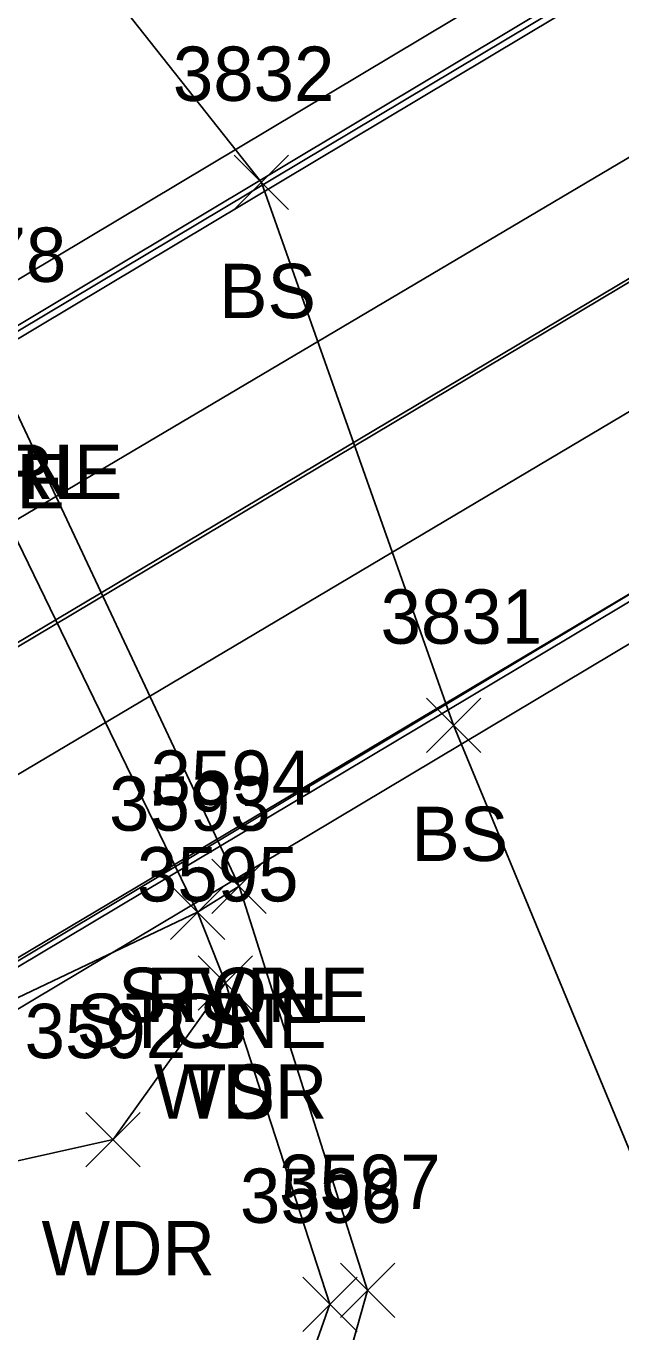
# Model space of a CAD drawing. Extents: x 1443590 to 1445966, y 578314 to 580556.
# Drawn here: x 1444226.98 to 1444248.89, y 578924.11 to 578972.2 of the extents above; entities that cross this region are included whole.
import ezdxf

# ---------------------------------------------------------------- set-up
doc = ezdxf.new("R2010")
doc.units = 0
for name, color, linetype in [('BB', 7, 'Continuous'), ('BDC', 7, 'Continuous'), ('BELB', 7, 'Continuous'), ('BF', 7, 'Continuous'), ('L_A', 7, 'Continuous'), ('L_I', 7, 'Continuous'), ('L_TIC', 7, 'Continuous'), ('LASF', 7, 'Continuous'), ('LAWA', 7, 'Continuous'), ('LAWE', 7, 'Continuous'), ('LELB', 7, 'Continuous')]:
    doc.layers.add(name, color=color, linetype=linetype)

msp = doc.modelspace()

# ---------------------------------------------------------------- linework, layer by layer
at = {"layer": 'BB'}
for points in [[(1444205.61, 578948.082), (1444265.76, 578984.059)], [(1444208.51, 578943.3), (1444268.791, 578978.975)], [(1444210.663, 578939.803), (1444271.012, 578975.796)], [(1444212.663, 578936.329), (1444272.861, 578972.041)], [(1444215.703, 578931.366), (1444275.895, 578967.159)]]:
    msp.add_lwpolyline(points, dxfattribs=at)
at = {"layer": 'BDC'}
for points in [[(1444393.513, 579062.489), (1444394.118, 579061.308), (1444330.705, 579023.404), (1444267.078, 578985.387), (1444205.127, 578948.274), (1444203.399, 578948.665), (1444203.223, 578948.843)], [(1444405.354, 579042.696), (1444404.549, 579043.555), (1444341.218, 579006.037), (1444277.67, 578968.005), (1444214.55, 578930.312), (1444214.603, 578929.77), (1444215.047, 578929.061)]]:
    msp.add_lwpolyline(points, dxfattribs=at)
at = {"layer": 'BELB'}
for points in [[(1444394.46, 579061.264), (1444330.853, 579023.124), (1444267.263, 578985.215), (1444204.094, 578947.486)], [(1444399.314, 579053.056), (1444336.08, 579014.873), (1444272.042, 578976.518), (1444209.069, 578939.026)], [(1444404.648, 579044.232), (1444341.196, 579006.183), (1444277.507, 578968.231), (1444214.381, 578930.41)]]:
    msp.add_lwpolyline(points, dxfattribs=at)
at = {"layer": 'BF'}
for points in [[(1444393.513, 579062.489), (1444330.042, 579024.651), (1444266.432, 578986.627), (1444203.223, 578948.843)], [(1444405.354, 579042.696), (1444342.263, 579004.958), (1444278.425, 578966.905), (1444215.047, 578929.061)]]:
    msp.add_lwpolyline(points, dxfattribs=at)
at = {"layer": 'L_TIC'}
for points in [[(1444234.646, 578965.441), (1444236.646, 578967.441)], [(1444236.646, 578965.441), (1444234.646, 578967.441)], [(1444241.727, 578945.45), (1444243.727, 578947.45)], [(1444243.727, 578945.45), (1444241.727, 578947.45)], [(1444241.727, 578945.45), (1444243.727, 578947.45)], [(1444243.727, 578945.45), (1444241.727, 578947.45)], [(1444233.825, 578939.518), (1444235.825, 578941.518)], [(1444235.825, 578939.518), (1444233.825, 578941.518)], [(1444233.825, 578939.518), (1444235.825, 578941.518)], [(1444235.825, 578939.518), (1444233.825, 578941.518)], [(1444232.298, 578938.564), (1444234.298, 578940.564)], [(1444234.298, 578938.564), (1444232.298, 578940.564)], [(1444232.298, 578938.564), (1444234.298, 578940.564)], [(1444234.298, 578938.564), (1444232.298, 578940.564)], [(1444233.323, 578935.96), (1444235.323, 578937.96)], [(1444235.323, 578935.96), (1444233.323, 578937.96)], [(1444233.323, 578935.96), (1444235.323, 578937.96)], [(1444235.323, 578935.96), (1444233.323, 578937.96)], [(1444229.186, 578930.189), (1444231.186, 578932.189)], [(1444231.186, 578930.189), (1444229.186, 578932.189)], [(1444238.555, 578924.633), (1444240.555, 578926.633)], [(1444240.555, 578924.633), (1444238.555, 578926.633)], [(1444237.172, 578924.123), (1444239.172, 578926.123)], [(1444239.172, 578924.123), (1444237.172, 578926.123)]]:
    msp.add_lwpolyline(points, dxfattribs=at)
at = {"layer": 'LASF'}
msp.add_lwpolyline([(1444215.961, 578931.063), (1444221.338, 578933.886), (1444233.298, 578939.564), (1444234.825, 578940.518)], dxfattribs=at)
at = {"layer": 'LAWA'}
msp.add_lwpolyline([(1444048.103, 578821.317), (1444063.675, 578832.306), (1444080.367, 578840.962), (1444085.338, 578844.038), (1444109.175, 578848.22), (1444135.339, 578861.472), (1444163.107, 578880.72), (1444179.566, 578893.485), (1444193.413, 578903.289), (1444214.902, 578918.812), (1444217.379, 578923.703), (1444222.652, 578929.511), (1444230.186, 578931.189), (1444234.323, 578936.96), (1444238.172, 578925.123), (1444234.94, 578915.96)], dxfattribs=at)
at = {"layer": 'LAWE'}
msp.add_lwpolyline([(1444132.863, 579092.153), (1444138.962, 579083.211), (1444141.194, 579057.076), (1444148.069, 579045.276), (1444167.245, 579025.017), (1444174.77, 579019.565), (1444188.422, 579002.667), (1444202.859, 578984.811), (1444211.076, 578975.971), (1444218.072, 578968.054), (1444223.321, 578965.926), (1444225.772, 578959.776), (1444234.825, 578940.518), (1444239.555, 578925.633), (1444236.716, 578915.571)], dxfattribs=at)
at = {"layer": 'LELB'}
for points in [[(1444242.727, 578946.45), (1444235.646, 578966.441), (1444217.42, 578989.468)], [(1444202.131, 578983.151), (1444209.603, 578974.712), (1444216.697, 578967.02), (1444221.206, 578964.775), (1444223.649, 578959.432), (1444233.298, 578939.564), (1444234.323, 578936.96)], [(1444242.727, 578946.45), (1444252.712, 578922.317)]]:
    msp.add_lwpolyline(points, dxfattribs=at)

# ---------------------------------------------------------------- texts
at = {"layer": 'L_A'}
for s, p in [('BS', (1444234.087, 578961.441)), ('STONE', (1444219.192, 578954.432)), ('STONE', (1444221.315, 578954.776)), ('RVRL', (1444222.339, 578954.776)), ('BS', (1444241.168, 578941.45)), ('BS', (1444241.168, 578941.45)), ('STONE', (1444230.368, 578935.518)), ('RVRL', (1444231.392, 578935.518)), ('STONE', (1444228.841, 578934.564)), ('TS', (1444231.708, 578934.564)), ('WDR', (1444231.686, 578931.96)), ('TS', (1444232.733, 578931.96)), ('WDR', (1444227.548, 578926.189))]:
    msp.add_text(s, height=2, dxfattribs=at).set_placement(p)
at = {"layer": 'L_I'}
for s, p in [('3832', (1444232.386, 578969.441)), ('3578', (1444222.512, 578962.776)), ('3578', (1444222.512, 578962.776)), ('3831', (1444240.035, 578949.45)), ('3831', (1444240.035, 578949.45)), ('3594', (1444231.565, 578943.518)), ('3594', (1444231.565, 578943.518)), ('3593', (1444230.038, 578942.564)), ('3593', (1444230.038, 578942.564)), ('3595', (1444231.064, 578939.96)), ('3595', (1444231.064, 578939.96)), ('3592', (1444226.926, 578934.189)), ('3597', (1444236.296, 578928.633)), ('3596', (1444234.857, 578928.123))]:
    msp.add_text(s, height=2, dxfattribs=at).set_placement(p)

doc.saveas('drawing.dxf')
